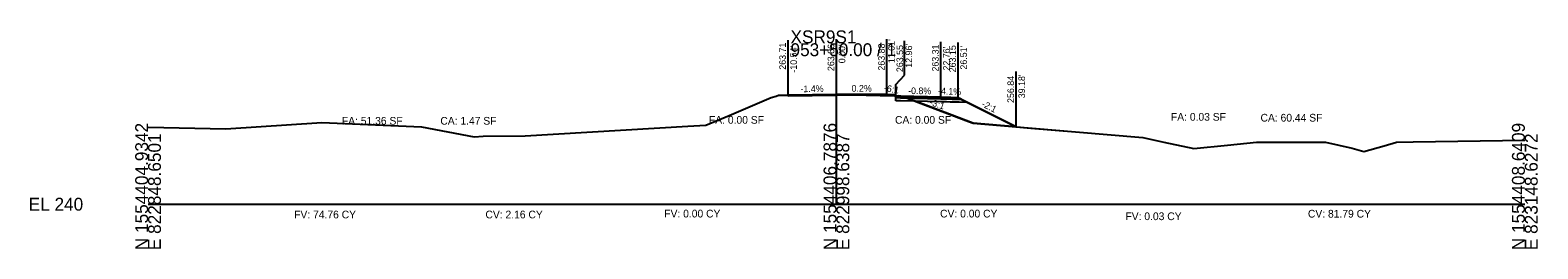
# Model space of a CAD drawing. Extents: x -26 to 823017, y -16 to 1558356.
# Drawn here: x -25.7 to 302.8, y 1490.3 to 1537.8 of the extents above; entities that cross this region are included whole.
import ezdxf

# ---------------------------------------------------------------- set-up
doc = ezdxf.new("R2010")
doc.units = 0
for name, color, linetype in [('ASPHALT_19MM1', 7, 'Continuous'), ('CONST_DCH', 7, 'Continuous'), ('CONST_LV3', 7, 'Continuous'), ('Draft_XS_Grid', 7, 'Continuous'), ('DTM_CORRIDOR', 7, 'Continuous'), ('DTM_P_FINISHED_GRADE2', 7, 'Continuous'), ('DTM_TEMP_DROP', 7, 'Continuous'), ('DTM_X_GROUND', 7, 'Continuous'), ('PROFILES_DCH_2', 7, 'Continuous'), ('XS_CELL', 7, 'Continuous'), ('XS_P_ASPHALT', 7, 'Continuous'), ('XS_P_DR_GRAVEL', 7, 'Continuous'), ('XS_P_GROUND', 7, 'Continuous'), ('XS_P_SHOULDER', 7, 'Continuous'), ('XS_P_SUBGRADE_GRANULAR', 7, 'Continuous'), ('XS_P_SUBGRADE_LEVELING', 7, 'Continuous'), ('XS_P_SUBGRADE_MILLING', 7, 'Continuous'), ('XS_P_SUBGRADE_UNDERCUT', 7, 'Continuous'), ('XS_P_TX_CLEARZONE', 7, 'Continuous'), ('XS_P_TX_FS_BS', 7, 'Continuous'), ('XS_SHEET_EW_TX_AREA', 7, 'Continuous'), ('XS_SHEET_EW_TX_VOLUME', 7, 'Continuous')]:
    doc.layers.add(name, color=color, linetype=linetype)

msp = doc.modelspace()

# ---------------------------------------------------------------- linework, layer by layer
at = {"layer": 'ASPHALT_19MM1'}
msp.add_lwpolyline([(163.93, 1523.36), (162.96, 1523.38), (162.96, 1523.19), (162.96, 1523.18), (163.93, 1523.15), (172.76, 1522.93), (172.76, 1523.01), (172.76, 1523.14), (163.93, 1523.36)], dxfattribs=at)
at = {"layer": 'CONST_DCH'}
msp.add_lwpolyline([(163.93, 1523.53), (162.96, 1523.55), (162.96, 1523.4), (162.96, 1523.38), (163.93, 1523.36), (172.76, 1523.14), (172.76, 1523.2), (172.76, 1523.31), (163.93, 1523.53)], dxfattribs=at)
at = {"layer": 'CONST_LV3'}
for points in [[(0, 1516.77), (16.98, 1516.4), (37.85, 1517.74), (59.61, 1516.81), (71.06, 1514.66), (73.03, 1514.8), (82.14, 1514.9), (117.64, 1517), (121.57, 1517.18), (126.6, 1519.28), (135.75, 1523.19), (136.88, 1523.53), (137.38, 1523.68), (139.46, 1523.71), (139.46, 1523.71)], [(150, 1523.86), (164, 1523.58)], [(161.01, 1523.88), (162.66, 1523.89), (162.9, 1523.89), (162.9, 1523.88), (162.9, 1523.88), (162.9, 1523.88), (162.9, 1523.88), (162.9, 1523.87), (162.9, 1523.87), (162.9, 1523.87), (162.9, 1523.87), (162.9, 1523.87), (162.9, 1523.87), (162.9, 1523.86), (162.9, 1523.86), (162.9, 1523.86), (162.9, 1523.86), (162.9, 1523.86), (162.9, 1523.86), (162.9, 1523.86), (162.9, 1523.86), (162.9, 1523.86), (162.9, 1523.85), (162.9, 1523.85), (162.9, 1523.85), (162.9, 1523.85), (162.9, 1523.85), (162.9, 1523.85), (162.9, 1523.85), (162.95, 1523.55), (162.95, 1523.55), (162.96, 1523.55), (163.93, 1523.53), (172.76, 1523.31), (174.91, 1523.22), (176.51, 1523.15), (181.38, 1520.73), (189.18, 1516.84), (192.37, 1516.57), (202.12, 1515.75), (216.73, 1514.49), (221.35, 1513.5), (227.9, 1512.14), (235.2, 1512.87), (241.53, 1513.49), (252.73, 1513.51), (256.6, 1513.52), (262.37, 1512.18), (264.89, 1511.43), (269.37, 1512.69), (272.06, 1513.5), (275.65, 1513.58), (300, 1513.93)], [(163.36, 1523.6), (163.36, 1523.6), (164, 1523.58)]]:
    msp.add_lwpolyline(points, dxfattribs=at)
at = {"layer": 'DTM_P_FINISHED_GRADE2'}
msp.add_lwpolyline([(139.46, 1523.71), (150, 1523.86), (161.01, 1523.88)], dxfattribs=at)
at = {"layer": 'DTM_X_GROUND'}
for points in [[(0, 1516.77), (16.98, 1516.4), (37.85, 1517.74), (59.61, 1516.81), (71.06, 1514.66), (73.03, 1514.8), (82.14, 1514.9), (117.64, 1517), (121.57, 1517.18), (126.6, 1519.28), (135.75, 1523.19), (136.88, 1523.53), (137.38, 1523.68), (140.7, 1523.72), (150.24, 1523.86), (162.66, 1523.89), (162.9, 1523.89), (162.9, 1523.88), (162.9, 1523.88), (162.9, 1523.88), (162.9, 1523.88), (162.9, 1523.87), (162.9, 1523.87), (162.9, 1523.87), (162.9, 1523.87), (162.9, 1523.87), (162.9, 1523.87), (162.9, 1523.86), (162.9, 1523.86), (162.9, 1523.86), (162.9, 1523.86), (162.9, 1523.86), (162.9, 1523.86), (162.9, 1523.86), (162.9, 1523.86), (162.9, 1523.86), (162.9, 1523.85), (162.9, 1523.85), (162.9, 1523.85), (162.9, 1523.85), (162.9, 1523.85), (162.9, 1523.85), (162.9, 1523.85), (162.95, 1523.55), (162.95, 1523.55), (162.96, 1523.55), (163.93, 1523.53), (172.76, 1523.31), (174.91, 1523.22), (176.51, 1523.15), (181.38, 1520.73), (189.18, 1516.84), (192.37, 1516.57), (202.12, 1515.75), (216.73, 1514.49), (221.35, 1513.5), (227.9, 1512.14), (235.2, 1512.87), (241.53, 1513.49), (252.73, 1513.51), (256.6, 1513.52), (262.37, 1512.18), (264.89, 1511.43), (269.37, 1512.69), (272.06, 1513.5), (275.65, 1513.58), (300, 1513.93)], [(0, 1516.77), (16.98, 1516.4), (37.85, 1517.74), (59.61, 1516.81), (71.06, 1514.66), (73.03, 1514.8), (82.14, 1514.9), (117.64, 1517), (121.57, 1517.18), (126.6, 1519.28), (135.75, 1523.19), (136.88, 1523.53), (137.38, 1523.68), (139.46, 1523.71), (139.46, 1523.71), (150, 1523.86), (150, 1523.86), (150, 1523.86), (150, 1523.86), (150, 1523.86), (150, 1523.86), (150, 1523.86), (150, 1523.86), (161.01, 1523.88), (161.01, 1523.88), (162.66, 1523.89), (162.9, 1523.89), (162.9, 1523.88), (162.9, 1523.88), (162.9, 1523.88), (162.9, 1523.88), (162.9, 1523.87), (162.9, 1523.87), (162.9, 1523.87), (162.9, 1523.87), (162.9, 1523.87), (162.9, 1523.87), (162.9, 1523.86), (162.9, 1523.86), (162.9, 1523.86), (162.9, 1523.86), (162.9, 1523.86), (162.9, 1523.86), (162.9, 1523.86), (162.9, 1523.86), (162.9, 1523.86), (162.9, 1523.85), (162.9, 1523.85), (162.9, 1523.85), (162.9, 1523.85), (162.9, 1523.85), (162.9, 1523.85), (162.9, 1523.85), (162.95, 1523.55), (162.95, 1523.55), (162.96, 1523.55), (163.93, 1523.53), (172.76, 1523.31), (174.91, 1523.22), (176.51, 1523.15), (181.38, 1520.73), (189.18, 1516.84), (192.37, 1516.57), (202.12, 1515.75), (216.73, 1514.49), (221.35, 1513.5), (227.9, 1512.14), (235.2, 1512.87), (241.53, 1513.49), (252.73, 1513.51), (256.6, 1513.52), (262.37, 1512.18), (264.89, 1511.43), (269.37, 1512.69), (272.06, 1513.5), (275.65, 1513.58), (300, 1513.93)], [(0, 1516.77), (16.98, 1516.4), (37.85, 1517.74), (59.61, 1516.81), (71.06, 1514.66), (73.03, 1514.8), (82.14, 1514.9), (117.64, 1517), (121.57, 1517.18), (126.6, 1519.28), (135.75, 1523.19), (136.88, 1523.53), (137.38, 1523.68), (140.7, 1523.72), (150.24, 1523.86), (162.66, 1523.56), (162.96, 1523.55), (163.01, 1523.54), (164.83, 1523.25), (170.63, 1521.07), (179.82, 1517.64), (202.12, 1515.75), (216.73, 1514.49), (221.35, 1513.5), (227.9, 1512.14), (235.2, 1512.87), (241.53, 1513.49), (252.73, 1513.51), (256.6, 1513.52), (262.37, 1512.18), (264.89, 1511.43), (269.37, 1512.69), (272.06, 1513.5), (275.65, 1513.58), (300, 1513.93)]]:
    msp.add_lwpolyline(points, dxfattribs=at)
at = {"layer": 'XS_CELL'}
for p, q in [((150, 1500), (150, 1535)), ((0, 1500), (150, 1500)), ((150, 1500), (300, 1500))]:
    msp.add_line(p, q, dxfattribs=at)
at = {"layer": 'XS_P_ASPHALT'}
msp.add_lwpolyline([(139.46, 1523.58), (150, 1523.73), (150, 1523.73), (161.01, 1523.76), (161.01, 1523.76), (161.01, 1523.88), (161.01, 1523.88), (150, 1523.86), (150, 1523.86), (139.46, 1523.71), (139.46, 1523.58)], dxfattribs=at)
at = {"layer": 'XS_P_DR_GRAVEL'}
msp.add_lwpolyline([(174.91, 1523.22), (172.76, 1523.31), (172.76, 1523.07), (172.76, 1522.93), (175.25, 1522.87), (177.18, 1522.82), (176.86, 1522.98), (176.51, 1523.15), (174.91, 1523.22)], dxfattribs=at)
at = {"layer": 'XS_P_GROUND'}
for points in [[(164.05, 1523.37), (164.05, 1523.37), (163.36, 1523.6)], [(189.18, 1516.84), (189.18, 1516.84), (179.82, 1517.64), (179.82, 1517.64), (179.82, 1517.64), (170.63, 1521.07), (170.63, 1521.07), (164.83, 1523.25), (164.83, 1523.25), (164.05, 1523.37)], [(189.18, 1516.84), (189.18, 1516.84), (179.82, 1517.64), (179.82, 1517.64), (179.82, 1517.64), (170.63, 1521.07), (170.63, 1521.07), (164.83, 1523.25), (164.83, 1523.25), (164.05, 1523.37)], [(176.51, 1523.15), (189.18, 1516.84)]]:
    msp.add_lwpolyline(points, dxfattribs=at)
at = {"layer": 'XS_P_SHOULDER'}
msp.add_lwpolyline([(172.76, 1523.31), (176.51, 1523.15)], dxfattribs=at)
at = {"layer": 'XS_P_SUBGRADE_GRANULAR'}
for points in [[(162.96, 1522.51), (162.96, 1523.55)], [(172.76, 1522.26), (163.93, 1522.48), (162.96, 1522.51)], [(178.59, 1522.12), (176.75, 1522.16), (174.77, 1522.21), (173.97, 1522.23), (172.76, 1522.26)]]:
    msp.add_lwpolyline(points, dxfattribs=at)
at = {"layer": 'XS_P_SUBGRADE_LEVELING'}
msp.add_lwpolyline([(161.01, 1523.76), (150.24, 1523.73), (150.24, 1523.73), (150, 1523.73), (150, 1523.73), (140.7, 1523.6), (140.7, 1523.6), (139.46, 1523.58)], dxfattribs=at)
msp.add_lwpolyline([(161.01, 1523.76), (150.24, 1523.73), (150.24, 1523.73), (150, 1523.73), (150, 1523.73), (140.7, 1523.6), (140.7, 1523.6), (139.46, 1523.58)], dxfattribs=at)
at = {"layer": 'XS_P_SUBGRADE_MILLING'}
msp.add_lwpolyline([(161.01, 1523.88), (161.01, 1523.76), (150.24, 1523.73), (150.24, 1523.73), (150, 1523.73), (150, 1523.73), (140.7, 1523.6), (140.7, 1523.6), (139.46, 1523.58), (139.46, 1523.71), (140.7, 1523.72), (140.7, 1523.72), (150, 1523.86), (150, 1523.86), (150.24, 1523.86), (150.24, 1523.86), (161.01, 1523.88)], dxfattribs=at)
at = {"layer": 'XS_P_SUBGRADE_UNDERCUT'}
for p, q in [((162.96, 1523.55), (164.83, 1523.25)), ((163.93, 1523.53), (162.96, 1523.55)), ((172.76, 1523.31), (163.93, 1523.53)), ((164.83, 1523.25), (178.79, 1518.02)), ((176.51, 1523.15), (172.76, 1523.31)), ((189.18, 1516.84), (176.51, 1523.15)), ((178.79, 1518.02), (179.82, 1517.64)), ((179.82, 1517.64), (189.18, 1516.84))]:
    msp.add_line(p, q, dxfattribs=at)
at = {"layer": 'XS_P_TX_CLEARZONE'}
for p, q in [((139.46, 1523.71), (139.46, 1535.71)), ((150, 1523.86), (150, 1535.86)), ((161.01, 1523.88), (161.01, 1535.88)), ((164.8, 1528.09), (164.8, 1535.55)), ((172.76, 1523.31), (172.76, 1535.31)), ((176.51, 1523.15), (176.51, 1535.15)), ((162.96, 1526.05), (164.8, 1528.09)), ((189.18, 1516.84), (189.18, 1528.84)), ((162.96, 1523.55), (162.96, 1526.05))]:
    msp.add_line(p, q, dxfattribs=at)

# ---------------------------------------------------------------- texts
at = {"layer": 'CONST_DCH'}
msp.add_text('X', height=0.24, dxfattribs=at).set_placement((189.11, 1516.72))
at = {"layer": 'Draft_XS_Grid'}
msp.add_text('-', height=0.0001, dxfattribs=at).set_placement((0, 1500))
at = {"layer": 'DTM_CORRIDOR'}
for p in [(162.88, 1523.43), (172.68, 1523.19)]:
    msp.add_text('X', height=0.24, dxfattribs=at).set_placement(p)
at = {"layer": 'DTM_TEMP_DROP'}
for p in [(139.38, 1523.59), (149.92, 1523.74), (160.93, 1523.76)]:
    msp.add_text('X', height=0.24, dxfattribs=at).set_placement(p)
at = {"layer": 'PROFILES_DCH_2'}
for p in [(163.28, 1523.48), (163.97, 1523.25), (189.11, 1516.72)]:
    msp.add_text('X', height=0.24, dxfattribs=at).set_placement(p)
at = {"layer": 'XS_CELL'}
for s, p in [('XSR9S1', (140, 1535)), ('953+50.00 / 1', (140, 1532.2)), ('EL 240', (-26, 1498.6))]:
    msp.add_text(s, height=2.8, dxfattribs=at).set_placement(p)
for s, p in [('N 1554404.9342', (0, 1490)), ('E 822848.6501', (2.8, 1490)), ('N 1554406.7876', (150, 1490)), ('E 822998.6387', (152.8, 1490)), ('N 1554408.6409', (300, 1490)), ('E 823148.6272', (302.8, 1490))]:
    msp.add_text(s, height=2.8, rotation=90, dxfattribs=at).set_placement(p)
at = {"layer": 'XS_P_ASPHALT'}
msp.add_text('X', height=0.24, dxfattribs=at).set_placement((189.11, 1516.72))
at = {"layer": 'XS_P_SHOULDER'}
msp.add_text('X', height=0.24, dxfattribs=at).set_placement((176.43, 1523.03))
at = {"layer": 'XS_P_TX_CLEARZONE'}
for s, p in [('263.71', (138.98, 1529.25)), ("-10.54'", (141.38, 1528.61)), ('263.86', (149.52, 1528.96)), ("0.00'", (151.92, 1530.65)), ('263.88', (160.53, 1529.06)), ("11.01'", (162.72, 1530.69)), ('263.55', (164.53, 1528.73)), ("12.96'", (166.49, 1529.68)), ('263.31', (172.28, 1528.85)), ('263.15', (176.03, 1528.69)), ("26.51'", (178.43, 1529.28)), ("22.76'", (174.68, 1529.07)), ('256.84', (188.7, 1522.02)), ("39.18'", (191.1, 1523.04))]:
    msp.add_text(s, height=1.44, rotation=90, dxfattribs=at).set_placement(p)
at = {"layer": 'XS_P_TX_FS_BS'}
for s, rotation, p in [('-1.4%', 0.812, (142.17, 1524.35)), ('0.2%', 0.1261, (153.3, 1524.47)), ('-6:1', 350.3602, (160.26, 1524.62)), ('-0.8%', 359.5606, (165.62, 1523.96)), ('-4.1%', 357.6453, (172.11, 1523.93)), ('-3:1', 341.5651, (170.17, 1521.61)), ('-2:1', 333.5313, (181.49, 1521.34))]:
    msp.add_text(s, height=1.44, rotation=rotation, dxfattribs=at).set_placement(p)
at = {"layer": 'XS_SHEET_EW_TX_AREA'}
for s, p in [('FA: 51.36 SF', (42.24, 1517.3)), ('CA: 1.47 SF', (63.69, 1517.3)), ('FA: 0.00 SF', (122.22, 1517.5)), ('CA: 0.00 SF', (162.76, 1517.5)), ('FA: 0.03 SF', (222.89, 1518.16)), ('CA: 60.44 SF', (242.41, 1517.97))]:
    msp.add_text(s, height=1.68, dxfattribs=at).set_placement(p)
at = {"layer": 'XS_SHEET_EW_TX_VOLUME'}
for s, p in [('FV: 74.76 CY', (31.83, 1496.92)), ('CV: 2.16 CY', (73.52, 1496.92)), ('FV: 0.00 CY', (112.48, 1497.12)), ('CV: 0.00 CY', (172.59, 1497.12)), ('FV: 0.03 CY', (212.97, 1496.54)), ('CV: 81.79 CY', (252.74, 1497.09))]:
    msp.add_text(s, height=1.68, dxfattribs=at).set_placement(p)

doc.saveas('drawing.dxf')
